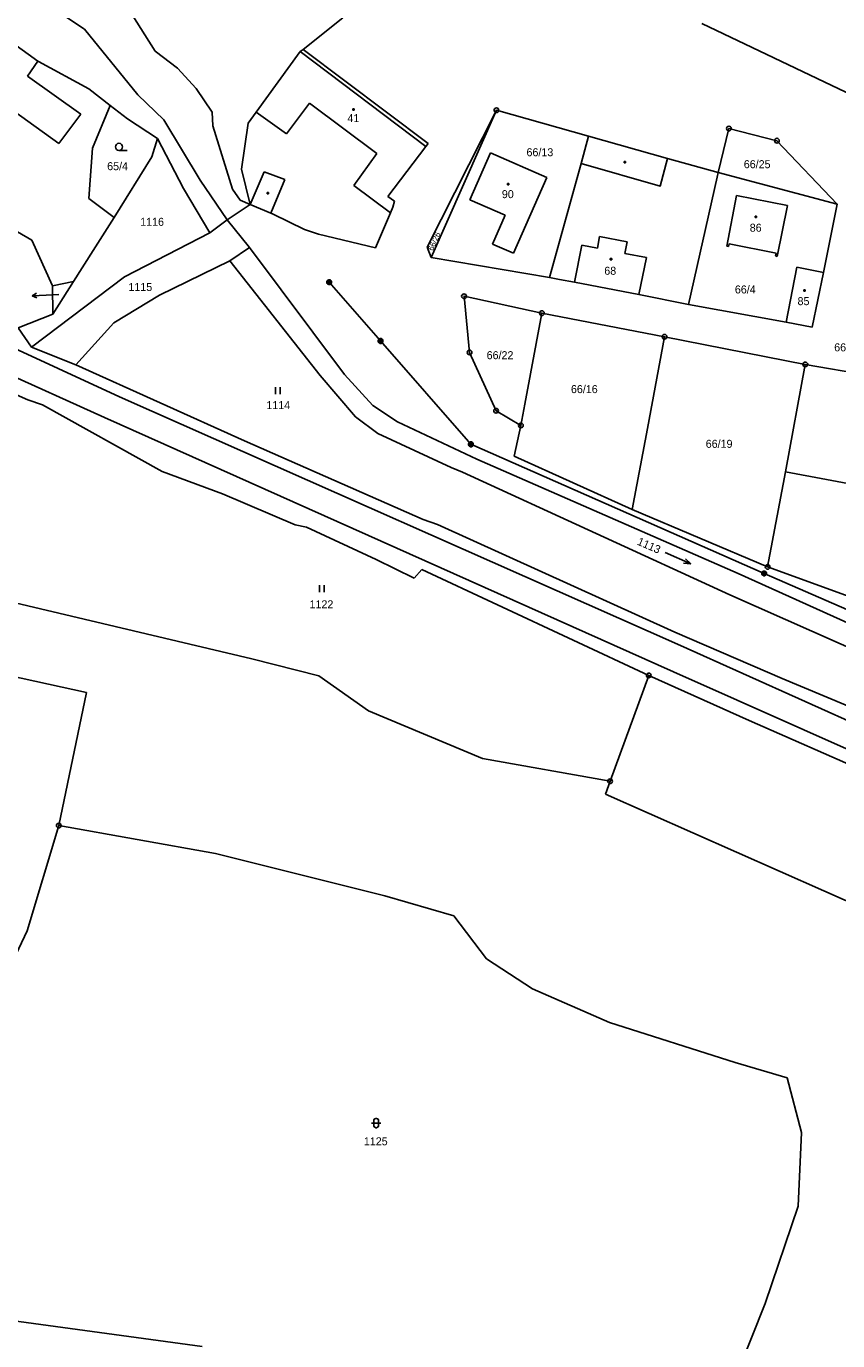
# Model space of a CAD drawing. Extents: x -796130 to -793145, y -1109506 to -1106267.
# Drawn here: x -794319.4 to -794147, y -1108157.6 to -1107878.4 of the extents above; entities that cross this region are included whole.
import ezdxf

# ---------------------------------------------------------------- set-up
doc = ezdxf.new("R2010")
doc.units = 0
for name, color, linetype in [('Komunikace', 7, 'Continuous'), ('Vrstva 1', 7, 'Continuous'), ('Vrstva 12', 7, 'Continuous'), ('Vrstva 14', 7, 'Continuous'), ('Vrstva 15', 7, 'Continuous'), ('Vrstva 16', 7, 'Continuous'), ('Vrstva 2', 7, 'Continuous'), ('Vrstva 23', 7, 'Continuous'), ('Vrstva 25', 7, 'Continuous'), ('Vrstva 26', 7, 'Continuous'), ('Vrstva 28', 7, 'Continuous')]:
    doc.layers.add(name, color=color, linetype=linetype)

msp = doc.modelspace()

# ---------------------------------------------------------------- linework, layer by layer
at = {"layer": 'Komunikace'}
msp.add_line((-794312.51, -1107935.34), (-794315.21, -1107935.48), dxfattribs=at)
at = {"layer": 'Vrstva 1'}
for p, q in [((-794314.42, -1107874.11), (-794307.09, -1107878.97)), ((-794292.06, -1107883.61), (-794297.29, -1107875.35)), ((-794260.61, -1107883.26), (-794252.16, -1107876.59)), ((-794175.87, -1107877.74), (-794108.67, -1107909.82)), ((-794316.94, -1107885.78), (-794326.45, -1107878.97)), ((-794307.09, -1107878.97), (-794295.69, -1107892.95)), ((-794287.26, -1107887.26), (-794292.06, -1107883.61)), ((-794270.57, -1107896.59), (-794261.2, -1107883.72)), ((-794261.2, -1107883.72), (-794260.61, -1107883.26)), ((-794260.61, -1107883.26), (-794234.06, -1107903.27)), ((-794316.82, -1107885.87), (-794316.94, -1107885.78)), ((-794306.16, -1107891.66), (-794316.82, -1107885.87)), ((-794283.34, -1107891.59), (-794287.26, -1107887.26)), ((-794306.16, -1107891.66), (-794301.59, -1107895.17)), ((-794279.9, -1107896.58), (-794283.34, -1107891.59)), ((-794301.59, -1107895.17), (-794305.34, -1107904.27)), ((-794301.59, -1107895.17), (-794297.91, -1107898)), ((-794295.69, -1107892.95), (-794290.18, -1107898.24)), ((-794291.55, -1107902.19), (-794297.91, -1107898)), ((-794290.18, -1107898.24), (-794282.48, -1107911.08)), ((-794279.82, -1107899.52), (-794279.9, -1107896.58)), ((-794272.27, -1107898.93), (-794270.57, -1107896.59)), ((-794219.53, -1107896.2), (-794234.22, -1107925.3)), ((-794219.53, -1107896.2), (-794233.43, -1107927.51)), ((-794199.95, -1107901.73), (-794219.53, -1107896.2)), ((-794275.61, -1107912.94), (-794279.82, -1107899.52)), ((-794273.67, -1107908.74), (-794272.27, -1107898.93)), ((-794172.43, -1107909.4), (-794170.15, -1107900.09)), ((-794170.15, -1107900.09), (-794159.93, -1107902.66)), ((-794292.75, -1107906.07), (-794291.55, -1107902.19)), ((-794291.55, -1107902.19), (-794286.05, -1107912.83)), ((-794234.51, -1107903.91), (-794242.59, -1107914.54)), ((-794234.06, -1107903.27), (-794234.51, -1107903.91)), ((-794201.55, -1107907.52), (-794199.95, -1107901.73)), ((-794183.21, -1107906.43), (-794199.95, -1107901.73)), ((-794159.93, -1107902.66), (-794147.1, -1107916.15)), ((-794305.34, -1107904.27), (-794306.15, -1107914.92)), ((-794300.78, -1107919), (-794292.75, -1107906.07)), ((-794225.17, -1107915.25), (-794220.79, -1107905.25)), ((-794220.79, -1107905.25), (-794208.81, -1107910.49)), ((-794172.43, -1107909.4), (-794183.21, -1107906.43)), ((-794271.87, -1107916.21), (-794273.67, -1107908.74)), ((-794208.29, -1107931.76), (-794201.55, -1107907.52)), ((-794172.66, -1107910.43), (-794172.43, -1107909.4)), ((-794147.1, -1107916.15), (-794172.43, -1107909.4)), ((-794276.72, -1107919.45), (-794282.48, -1107911.08)), ((-794208.81, -1107910.49), (-794215.91, -1107926.56)), ((-794178.69, -1107937.44), (-794172.66, -1107910.43)), ((-794306.15, -1107914.92), (-794300.78, -1107919)), ((-794286.05, -1107912.83), (-794280.39, -1107922.27)), ((-794273.97, -1107915.33), (-794275.61, -1107912.94)), ((-794242.59, -1107914.54), (-794241.22, -1107915.54)), ((-794170.6, -1107925.09), (-794168.5, -1107914.29)), ((-794168.5, -1107914.29), (-794157.69, -1107916.42)), ((-794332.4, -1107915.66), (-794318.28, -1107923.8)), ((-794276.72, -1107919.45), (-794271.87, -1107916.21)), ((-794271.87, -1107916.21), (-794273.97, -1107915.33)), ((-794267.43, -1107918.08), (-794271.87, -1107916.21)), ((-794242.04, -1107917.96), (-794245.22, -1107925.43)), ((-794241.55, -1107916.82), (-794242.04, -1107917.96)), ((-794241.22, -1107915.54), (-794241.55, -1107916.82)), ((-794217.68, -1107918.49), (-794225.17, -1107915.25)), ((-794157.69, -1107916.42), (-794159.85, -1107927.24)), ((-794150.02, -1107930.66), (-794147.1, -1107916.15)), ((-794305.24, -1107926.02), (-794300.78, -1107919)), ((-794276.72, -1107919.45), (-794280.39, -1107922.27)), ((-794272, -1107925.37), (-794276.72, -1107919.45)), ((-794266.97, -1107918.27), (-794267.43, -1107918.08)), ((-794260.34, -1107921.51), (-794266.97, -1107918.27)), ((-794220.34, -1107924.65), (-794217.68, -1107918.49)), ((-794280.39, -1107922.27), (-794298.59, -1107931.59)), ((-794257.33, -1107922.52), (-794260.34, -1107921.51)), ((-794245.22, -1107925.43), (-794257.33, -1107922.52)), ((-794318.28, -1107923.8), (-794313.85, -1107933.49)), ((-794305.24, -1107926.02), (-794309.41, -1107932.6)), ((-794276.19, -1107928.2), (-794272, -1107925.37)), ((-794272, -1107925.37), (-794251.79, -1107952.37)), ((-794234.22, -1107925.3), (-794233.43, -1107927.51)), ((-794215.91, -1107926.56), (-794220.34, -1107924.65)), ((-794170.21, -1107925.17), (-794170.6, -1107925.09)), ((-794170.09, -1107924.58), (-794170.21, -1107925.17)), ((-794160.12, -1107926.58), (-794170.09, -1107924.58)), ((-794291.13, -1107935.48), (-794276.19, -1107928.2)), ((-794276.19, -1107928.2), (-794256.97, -1107952.56)), ((-794233.43, -1107927.51), (-794208.29, -1107931.76)), ((-794160.24, -1107927.16), (-794160.12, -1107926.58)), ((-794159.85, -1107927.24), (-794160.24, -1107927.16)), ((-794298.59, -1107931.59), (-794318.35, -1107946.5)), ((-794208.29, -1107931.76), (-794206.12, -1107932.14)), ((-794155.69, -1107929.51), (-794157.97, -1107941.21)), ((-794150.02, -1107930.66), (-794155.69, -1107929.51)), ((-794152.42, -1107942.31), (-794150.02, -1107930.66)), ((-794313.85, -1107933.49), (-794309.41, -1107932.6)), ((-794313.79, -1107939.52), (-794313.85, -1107933.49)), ((-794309.41, -1107932.6), (-794313.79, -1107939.52)), ((-794206.12, -1107932.14), (-794202.94, -1107932.7)), ((-794202.94, -1107932.7), (-794189.25, -1107935.37)), ((-794300.8, -1107941.33), (-794291.13, -1107935.48)), ((-794225.25, -1107947.66), (-794226.42, -1107935.7)), ((-794226.42, -1107935.7), (-794209.86, -1107939.31)), ((-794189.25, -1107935.37), (-794178.69, -1107937.44)), ((-794178.69, -1107937.44), (-794157.97, -1107941.21)), ((-794321.16, -1107942.45), (-794313.79, -1107939.52)), ((-794213.48, -1107958.65), (-794209.86, -1107939.31)), ((-794183.81, -1107944.32), (-794209.86, -1107939.31)), ((-794318.35, -1107946.5), (-794321.16, -1107942.45)), ((-794308.91, -1107950.3), (-794300.8, -1107941.33)), ((-794157.97, -1107941.21), (-794152.42, -1107942.31)), ((-794187.46, -1107963.8), (-794183.81, -1107944.32)), ((-794183.81, -1107944.32), (-794153.9, -1107950.19)), ((-794318.35, -1107946.5), (-794308.91, -1107950.3)), ((-794219.61, -1107960.04), (-794225.25, -1107947.66)), ((-794273.08, -1107966.41), (-794308.91, -1107950.3)), ((-794153.9, -1107950.19), (-794158.08, -1107973.04)), ((-794153.9, -1107950.19), (-794122.25, -1107955.65)), ((-794319.11, -1107957.73), (-794327.03, -1107954.23)), ((-794256.97, -1107952.56), (-794249.44, -1107961.36)), ((-794251.79, -1107952.37), (-794245.81, -1107958.96)), ((-794315.97, -1107958.78), (-794319.11, -1107957.73)), ((-794290.58, -1107972.98), (-794315.97, -1107958.78)), ((-794245.81, -1107958.96), (-794240.54, -1107962.38)), ((-794214.33, -1107963.17), (-794213.48, -1107958.65)), ((-794249.44, -1107961.36), (-794244.7, -1107964.86)), ((-794240.54, -1107962.38), (-794223.66, -1107970.32)), ((-794214.33, -1107963.17), (-794219.61, -1107960.04)), ((-794244.7, -1107964.86), (-794229.16, -1107972.08)), ((-794215.78, -1107969.7), (-794214.33, -1107963.17)), ((-794190.68, -1107981), (-794187.46, -1107963.8)), ((-794235.12, -1107983.14), (-794273.08, -1107966.41)), ((-794223.66, -1107970.32), (-794168.15, -1107994.62)), ((-794215.78, -1107969.7), (-794190.68, -1107981)), ((-794277.72, -1107977.69), (-794290.58, -1107972.98)), ((-794229.16, -1107972.08), (-794226.72, -1107973.12)), ((-794226.72, -1107973.12), (-794169.94, -1107999.17)), ((-794158.08, -1107973.04), (-794161.9, -1107993.23)), ((-794158.08, -1107973.04), (-794126.24, -1107978.94)), ((-794262.27, -1107984.27), (-794277.72, -1107977.69)), ((-794190.68, -1107981), (-794161.9, -1107993.23)), ((-794259.87, -1107984.8), (-794262.27, -1107984.27)), ((-794245.08, -1107991.64), (-794259.87, -1107984.8)), ((-794235.12, -1107983.14), (-794232.02, -1107984.21)), ((-794232.02, -1107984.21), (-794181.64, -1108007.06)), ((-794236.99, -1107995.63), (-794245.08, -1107991.64)), ((-794130.79, -1108004.55), (-794161.9, -1107993.23)), ((-794271.47, -1108012.73), (-794345.16, -1107995.36)), ((-794235.39, -1107993.74), (-794236.99, -1107995.63)), ((-794187.18, -1108016.27), (-794235.39, -1107993.74)), ((-794168.15, -1107994.62), (-794093.53, -1108028.31)), ((-794169.94, -1107999.17), (-794095.11, -1108032.28)), ((-794181.64, -1108007.06), (-794158.82, -1108016.94)), ((-794361.62, -1108007.82), (-794306.61, -1108019.91)), ((-794271.47, -1108012.73), (-794257.27, -1108016.4)), ((-794257.27, -1108016.4), (-794246.73, -1108023.78)), ((-794195.37, -1108038.78), (-794187.18, -1108016.27)), ((-794165.82, -1108025.89), (-794187.18, -1108016.27)), ((-794158.82, -1108016.94), (-794103.82, -1108039.99)), ((-794312.53, -1108048.19), (-794306.61, -1108019.91)), ((-794246.73, -1108023.78), (-794222.49, -1108033.95)), ((-794129.88, -1108041.67), (-794165.82, -1108025.89)), ((-794222.49, -1108033.95), (-794195.37, -1108038.78)), ((-794196.39, -1108041.5), (-794195.37, -1108038.78)), ((-794196.39, -1108041.5), (-794112.13, -1108078.79)), ((-794312.53, -1108048.19), (-794319.23, -1108070.58)), ((-794279.21, -1108054.14), (-794312.53, -1108048.19)), ((-794243.26, -1108063.12), (-794279.21, -1108054.14)), ((-794228.59, -1108067.34), (-794243.26, -1108063.12)), ((-794221.67, -1108076.47), (-794228.59, -1108067.34)), ((-794319.23, -1108070.58), (-794326.93, -1108086.75)), ((-794211.84, -1108082.84), (-794221.67, -1108076.47)), ((-794195.54, -1108090.03), (-794211.84, -1108082.84)), ((-794168.82, -1108098.54), (-794195.54, -1108090.03)), ((-794157.76, -1108101.76), (-794168.82, -1108098.54)), ((-794154.74, -1108113.41), (-794157.76, -1108101.76)), ((-794155.4, -1108129.02), (-794154.74, -1108113.41)), ((-794162.41, -1108149.76), (-794155.4, -1108129.02)), ((-794168.95, -1108165.96), (-794162.41, -1108149.76)), ((-794325.8, -1108152.88), (-794282.07, -1108158.86))]:
    msp.add_line(p, q, dxfattribs=at)
at = {"layer": 'Vrstva 12'}
for p, q in [((-794244.14, -1107945.22), (-794255.06, -1107932.73)), ((-794224.95, -1107967.18), (-794244.14, -1107945.22)), ((-794162.66, -1107994.6), (-794224.95, -1107967.18)), ((-794096.16, -1108023.73), (-794162.66, -1107994.6))]:
    msp.add_line(p, q, dxfattribs=at)
at = {"layer": 'Vrstva 16'}
for p, q in [((-794318.206, -1107935.632), (-794317.232, -1107935.082)), ((-794315.21, -1107935.48), (-794318.206, -1107935.632)), ((-794318.206, -1107935.632), (-794317.182, -1107936.08))]:
    msp.add_line(p, q, dxfattribs=at)
at = {"layer": 'Vrstva 2'}
for p, q in [((-794234.51, -1107903.91), (-794261.2, -1107883.72)), ((-794316.94, -1107885.78), (-794319.15, -1107888.97)), ((-794312.5, -1107903.24), (-794333.17, -1107888.4)), ((-794319.15, -1107888.97), (-794307.86, -1107897.03)), ((-794259.23, -1107894.68), (-794264.12, -1107901.2)), ((-794259.23, -1107894.68), (-794244.96, -1107905.41)), ((-794307.86, -1107897.03), (-794312.5, -1107903.24)), ((-794264.12, -1107901.2), (-794270.57, -1107896.59)), ((-794244.96, -1107905.41), (-794249.83, -1107912.19)), ((-794299.63, -1107957.06), (-794407.86, -1107907.36)), ((-794271.87, -1107916.21), (-794268.89, -1107909.28)), ((-794268.89, -1107909.28), (-794264.52, -1107910.89)), ((-794264.52, -1107910.89), (-794267.43, -1107918.08)), ((-794249.83, -1107912.19), (-794242.04, -1107917.96)), ((-794198.07, -1107925.48), (-794197.6, -1107923.01)), ((-794197.6, -1107923.01), (-794191.75, -1107924.17)), ((-794202.94, -1107932.7), (-794201.38, -1107924.84)), ((-794201.38, -1107924.84), (-794198.07, -1107925.48)), ((-794191.75, -1107924.17), (-794192.22, -1107926.61)), ((-794192.22, -1107926.61), (-794187.63, -1107927.49)), ((-794187.63, -1107927.49), (-794189.25, -1107935.37)), ((-794361.74, -1107934.98), (-794302.78, -1107961.45)), ((-794180.45, -1108009.94), (-794299.63, -1107957.06)), ((-794302.78, -1107961.45), (-794181.93, -1108015.5)), ((-794122.52, -1108035.9), (-794180.45, -1108009.94)), ((-794181.93, -1108015.5), (-794118.39, -1108043.8))]:
    msp.add_line(p, q, dxfattribs=at)
msp.add_lwpolyline([(-794183.21, -1107906.43), (-794184.73, -1107912.3), (-794201.55, -1107907.52)], dxfattribs=at)
at = {"layer": 'Vrstva 23'}
for p, q in [((-794299.73, -1107904.72), (-794297.98, -1107904.72)), ((-794266.45, -1107956.52), (-794266.45, -1107955.02)), ((-794265.45, -1107955.02), (-794265.45, -1107956.52)), ((-794183.71, -1107990.172), (-794178.209, -1107992.567)), ((-794178.209, -1107992.567), (-794179.784, -1107992.427)), ((-794178.209, -1107992.567), (-794179.385, -1107991.51)), ((-794257.13, -1107998.57), (-794257.13, -1107997.07)), ((-794256.13, -1107997.07), (-794256.13, -1107998.57)), ((-794245.58, -1108110.8), (-794245.48, -1108110.6)), ((-794245.48, -1108110.6), (-794245.38, -1108110.5)), ((-794245.38, -1108110.5), (-794245.18, -1108110.4)), ((-794245.18, -1108110.4), (-794244.98, -1108110.4)), ((-794244.98, -1108110.4), (-794244.78, -1108110.5)), ((-794244.78, -1108110.5), (-794244.68, -1108110.6)), ((-794244.68, -1108110.6), (-794244.58, -1108110.8)), ((-794246.08, -1108111.4), (-794244.08, -1108111.4)), ((-794245.58, -1108112), (-794245.58, -1108110.8)), ((-794245.48, -1108112.2), (-794245.58, -1108112)), ((-794245.38, -1108112.3), (-794245.48, -1108112.2)), ((-794245.18, -1108112.4), (-794245.38, -1108112.3)), ((-794244.98, -1108112.4), (-794245.18, -1108112.4)), ((-794244.78, -1108112.3), (-794244.98, -1108112.4)), ((-794244.68, -1108112.2), (-794244.78, -1108112.3)), ((-794244.58, -1108112), (-794244.68, -1108112.2)), ((-794244.58, -1108110.8), (-794244.58, -1108112))]:
    msp.add_line(p, q, dxfattribs=at)
msp.add_circle((-794299.73, -1107903.97), 0.75, dxfattribs=at)
at = {"layer": 'Vrstva 25'}
for p, q in [((-794250.04, -1107895.86), (-794249.74, -1107895.86)), ((-794250.04, -1107896.16), (-794250.04, -1107895.86)), ((-794249.74, -1107896.16), (-794250.04, -1107896.16)), ((-794249.74, -1107895.86), (-794249.74, -1107896.16)), ((-794192.39, -1107907.1), (-794192.09, -1107907.1)), ((-794192.39, -1107907.4), (-794192.39, -1107907.1)), ((-794192.09, -1107907.4), (-794192.39, -1107907.4)), ((-794192.09, -1107907.1), (-794192.09, -1107907.4)), ((-794217.17, -1107911.73), (-794216.87, -1107911.73)), ((-794217.17, -1107912.03), (-794217.17, -1107911.73)), ((-794216.87, -1107912.03), (-794217.17, -1107912.03)), ((-794216.87, -1107911.73), (-794216.87, -1107912.03)), ((-794268.26, -1107913.66), (-794267.96, -1107913.66)), ((-794268.26, -1107913.96), (-794268.26, -1107913.66)), ((-794267.96, -1107913.96), (-794268.26, -1107913.96)), ((-794267.96, -1107913.66), (-794267.96, -1107913.96)), ((-794164.55, -1107918.67), (-794164.25, -1107918.67)), ((-794164.55, -1107918.97), (-794164.55, -1107918.67)), ((-794164.25, -1107918.97), (-794164.55, -1107918.97)), ((-794164.25, -1107918.67), (-794164.25, -1107918.97)), ((-794195.33, -1107927.67), (-794195.03, -1107927.67)), ((-794195.33, -1107927.97), (-794195.33, -1107927.67)), ((-794195.03, -1107927.97), (-794195.33, -1107927.97)), ((-794195.03, -1107927.67), (-794195.03, -1107927.97)), ((-794154.2, -1107934.33), (-794153.9, -1107934.33)), ((-794154.2, -1107934.63), (-794154.2, -1107934.33)), ((-794153.9, -1107934.63), (-794154.2, -1107934.63)), ((-794153.9, -1107934.33), (-794153.9, -1107934.63))]:
    msp.add_line(p, q, dxfattribs=at)
at = {"layer": 'Vrstva 26'}
for p, q in [((-794255.56, -1107932.63), (-794255.46, -1107932.43)), ((-794255.56, -1107932.83), (-794255.56, -1107932.63)), ((-794255.46, -1107933.03), (-794255.56, -1107932.83)), ((-794255.46, -1107932.43), (-794255.36, -1107932.33)), ((-794255.36, -1107933.13), (-794255.46, -1107933.03)), ((-794255.36, -1107932.33), (-794255.16, -1107932.23)), ((-794255.36, -1107932.53), (-794255.36, -1107932.93)), ((-794255.36, -1107932.93), (-794255.16, -1107933.03)), ((-794255.16, -1107933.23), (-794255.36, -1107933.13)), ((-794255.16, -1107932.23), (-794254.96, -1107932.23)), ((-794255.16, -1107933.03), (-794255.16, -1107932.43)), ((-794255.16, -1107932.43), (-794254.96, -1107932.43)), ((-794254.96, -1107933.23), (-794255.16, -1107933.23)), ((-794254.96, -1107932.23), (-794254.76, -1107932.33)), ((-794254.96, -1107932.43), (-794254.96, -1107933.03)), ((-794254.96, -1107933.03), (-794254.76, -1107932.93)), ((-794254.76, -1107933.13), (-794254.96, -1107933.23)), ((-794254.76, -1107932.33), (-794254.66, -1107932.43)), ((-794254.76, -1107932.93), (-794254.76, -1107932.53)), ((-794254.66, -1107933.03), (-794254.76, -1107933.13)), ((-794254.66, -1107932.43), (-794254.56, -1107932.63)), ((-794254.56, -1107932.83), (-794254.66, -1107933.03)), ((-794254.56, -1107932.63), (-794254.56, -1107932.83)), ((-794244.64, -1107945.12), (-794244.54, -1107944.92)), ((-794244.64, -1107945.32), (-794244.64, -1107945.12)), ((-794244.54, -1107945.52), (-794244.64, -1107945.32)), ((-794244.54, -1107944.92), (-794244.44, -1107944.82)), ((-794244.44, -1107945.62), (-794244.54, -1107945.52)), ((-794244.44, -1107944.82), (-794244.24, -1107944.72)), ((-794244.44, -1107945.02), (-794244.44, -1107945.42)), ((-794244.44, -1107945.42), (-794244.24, -1107945.52)), ((-794244.24, -1107945.72), (-794244.44, -1107945.62)), ((-794244.24, -1107944.72), (-794244.04, -1107944.72)), ((-794244.24, -1107945.52), (-794244.24, -1107944.92)), ((-794244.24, -1107944.92), (-794244.04, -1107944.92)), ((-794244.04, -1107945.72), (-794244.24, -1107945.72)), ((-794244.04, -1107944.72), (-794243.84, -1107944.82)), ((-794244.04, -1107944.92), (-794244.04, -1107945.52)), ((-794244.04, -1107945.52), (-794243.84, -1107945.42)), ((-794243.84, -1107945.62), (-794244.04, -1107945.72)), ((-794243.84, -1107944.82), (-794243.74, -1107944.92)), ((-794243.84, -1107945.42), (-794243.84, -1107945.02)), ((-794243.74, -1107945.52), (-794243.84, -1107945.62)), ((-794243.74, -1107944.92), (-794243.64, -1107945.12)), ((-794243.64, -1107945.32), (-794243.74, -1107945.52)), ((-794243.64, -1107945.12), (-794243.64, -1107945.32)), ((-794225.45, -1107967.08), (-794225.35, -1107966.88)), ((-794225.45, -1107967.28), (-794225.45, -1107967.08)), ((-794225.35, -1107967.48), (-794225.45, -1107967.28)), ((-794225.35, -1107966.88), (-794225.25, -1107966.78)), ((-794225.25, -1107967.58), (-794225.35, -1107967.48)), ((-794225.25, -1107966.78), (-794225.05, -1107966.68)), ((-794225.25, -1107966.98), (-794225.25, -1107967.38)), ((-794225.25, -1107967.38), (-794225.05, -1107967.48)), ((-794225.05, -1107967.68), (-794225.25, -1107967.58)), ((-794225.05, -1107966.68), (-794224.85, -1107966.68)), ((-794225.05, -1107967.48), (-794225.05, -1107966.88)), ((-794225.05, -1107966.88), (-794224.85, -1107966.88)), ((-794224.85, -1107967.68), (-794225.05, -1107967.68)), ((-794224.85, -1107966.68), (-794224.65, -1107966.78)), ((-794224.85, -1107966.88), (-794224.85, -1107967.48)), ((-794224.85, -1107967.48), (-794224.65, -1107967.38)), ((-794224.65, -1107967.58), (-794224.85, -1107967.68)), ((-794224.65, -1107966.78), (-794224.55, -1107966.88)), ((-794224.65, -1107967.38), (-794224.65, -1107966.98)), ((-794224.55, -1107967.48), (-794224.65, -1107967.58)), ((-794224.55, -1107966.88), (-794224.45, -1107967.08)), ((-794224.45, -1107967.28), (-794224.55, -1107967.48)), ((-794224.45, -1107967.08), (-794224.45, -1107967.28)), ((-794163.16, -1107994.5), (-794163.06, -1107994.3)), ((-794163.16, -1107994.7), (-794163.16, -1107994.5)), ((-794163.06, -1107994.9), (-794163.16, -1107994.7)), ((-794163.06, -1107994.3), (-794162.96, -1107994.2)), ((-794162.96, -1107995), (-794163.06, -1107994.9)), ((-794162.96, -1107994.2), (-794162.76, -1107994.1)), ((-794162.96, -1107994.4), (-794162.96, -1107994.8)), ((-794162.96, -1107994.8), (-794162.76, -1107994.9)), ((-794162.76, -1107995.1), (-794162.96, -1107995)), ((-794162.76, -1107994.1), (-794162.56, -1107994.1)), ((-794162.76, -1107994.9), (-794162.76, -1107994.3)), ((-794162.76, -1107994.3), (-794162.56, -1107994.3)), ((-794162.56, -1107995.1), (-794162.76, -1107995.1)), ((-794162.56, -1107994.1), (-794162.36, -1107994.2)), ((-794162.56, -1107994.3), (-794162.56, -1107994.9)), ((-794162.56, -1107994.9), (-794162.36, -1107994.8)), ((-794162.36, -1107995), (-794162.56, -1107995.1)), ((-794162.36, -1107994.2), (-794162.26, -1107994.3)), ((-794162.36, -1107994.8), (-794162.36, -1107994.4)), ((-794162.26, -1107994.9), (-794162.36, -1107995)), ((-794162.26, -1107994.3), (-794162.16, -1107994.5)), ((-794162.16, -1107994.7), (-794162.26, -1107994.9)), ((-794162.16, -1107994.5), (-794162.16, -1107994.7))]:
    msp.add_line(p, q, dxfattribs=at)
at = {"layer": 'Vrstva 28'}
for centre, radius in [((-794219.53, -1107896.2), 0.5), ((-794219.53, -1107896.2), 0.01), ((-794170.15, -1107900.09), 0.5), ((-794170.15, -1107900.09), 0.5), ((-794170.15, -1107900.09), 0.01), ((-794170.15, -1107900.09), 0.01), ((-794159.93, -1107902.66), 0.5), ((-794159.93, -1107902.66), 0.01), ((-794226.42, -1107935.7), 0.5), ((-794226.42, -1107935.7), 0.01), ((-794209.86, -1107939.31), 0.5), ((-794209.86, -1107939.31), 0.01), ((-794183.81, -1107944.32), 0.5), ((-794183.81, -1107944.32), 0.01), ((-794225.25, -1107947.66), 0.5), ((-794225.25, -1107947.66), 0.01), ((-794153.9, -1107950.19), 0.5), ((-794153.9, -1107950.19), 0.01), ((-794219.61, -1107960.04), 0.5), ((-794219.61, -1107960.04), 0.01), ((-794214.33, -1107963.17), 0.5), ((-794214.33, -1107963.17), 0.01), ((-794161.9, -1107993.23), 0.5), ((-794161.9, -1107993.23), 0.01), ((-794187.18, -1108016.27), 0.5), ((-794187.18, -1108016.27), 0.01), ((-794195.37, -1108038.78), 0.5), ((-794195.37, -1108038.78), 0.01), ((-794312.53, -1108048.19), 0.5), ((-794312.53, -1108048.19), 0.01)]:
    msp.add_circle(centre, radius, dxfattribs=at)

# ---------------------------------------------------------------- texts
at = {"layer": 'Vrstva 14'}
for s, height, p in [('66/13', 1.7, (-794213.14, -1107905.97)), ('66/25', 1.7, (-794166.976, -1107908.51)), ('65/4', 1.7, (-794302.24, -1107908.93)), ('1116', 1.7, (-794295.226, -1107920.75)), ('1115', 1.7, (-794297.723, -1107934.6)), ('66/4', 1.7, (-794168.87, -1107935.12)), ('65/12', 0.1, (-794312.51, -1107935.34)), ('66/2', 1.7, (-794147.76, -1107947.42)), ('66/22', 1.7, (-794221.61, -1107949.09)), ('66/16', 1.7, (-794203.7, -1107956.3)), ('1114', 1.7, (-794268.412, -1107959.7)), ('66/19', 1.7, (-794175.06, -1107967.92)), ('1122', 1.7, (-794259.243, -1108002.02)), ('1125', 1.7, (-794247.699, -1108116.12))]:
    msp.add_text(s, height=height, dxfattribs=at).set_placement(p)
for s, height, rotation, p in [('66/26', 1.22, 65.7, (-794233.036, -1107926.156)), ('1113', 1.7, 336.6, (-794189.768, -1107988.443))]:
    msp.add_text(s, height=height, rotation=rotation, dxfattribs=at).set_placement(p)
at = {"layer": 'Vrstva 15'}
for s, p in [('41', (-794251.19, -1107898.72)), ('90', (-794218.38, -1107914.87)), ('86', (-794165.71, -1107922)), ('68', (-794196.61, -1107931.15)), ('85', (-794155.55, -1107937.61))]:
    msp.add_text(s, height=1.7, dxfattribs=at).set_placement(p)

doc.saveas('drawing.dxf')
